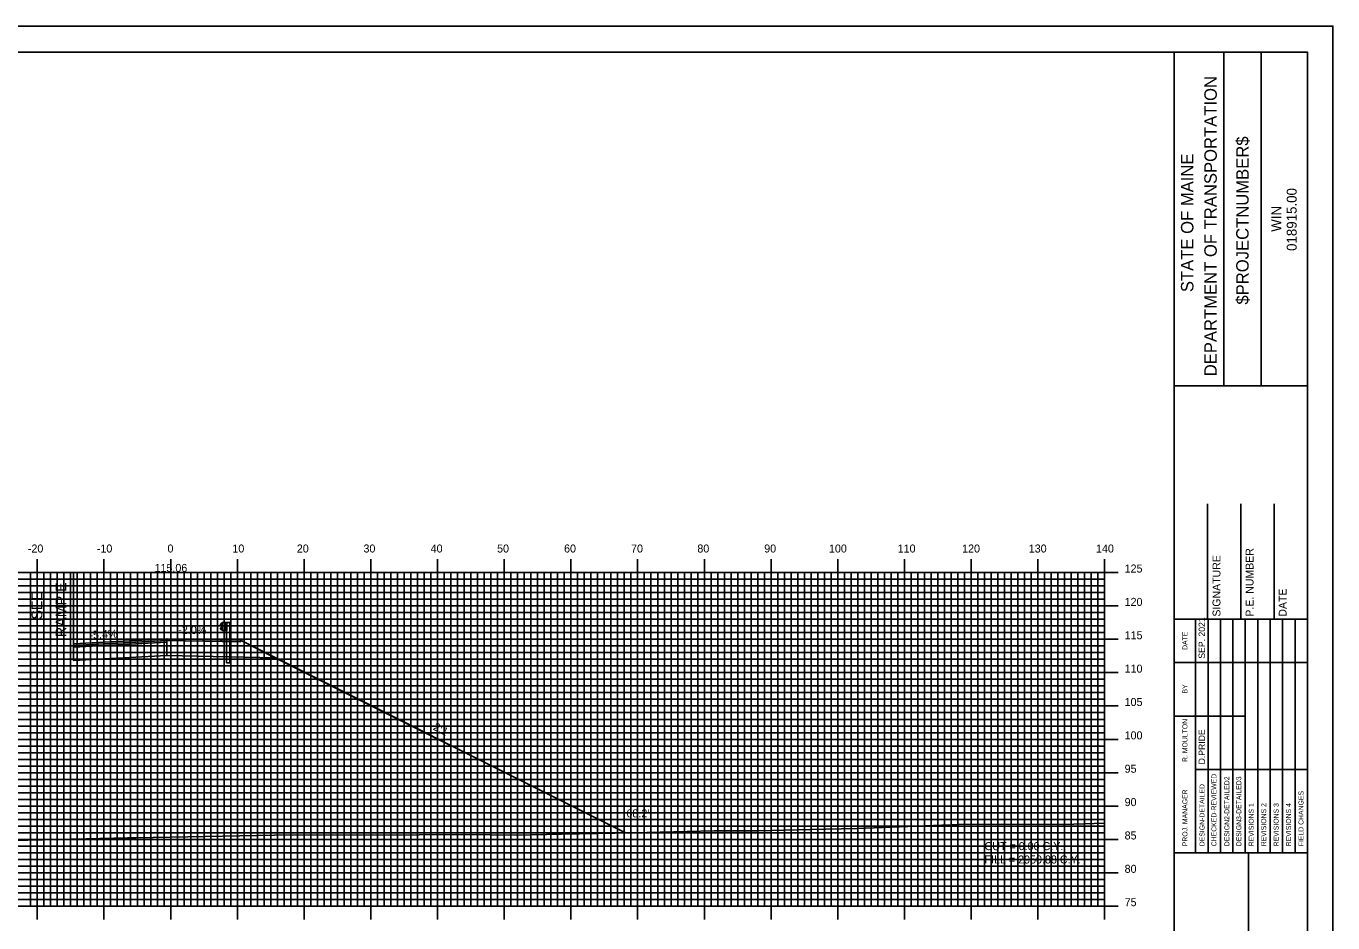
# Model space of a CAD drawing. Extents: x 92 to 435, y -1658 to -1438.
# Drawn here: x 236 to 431.8, y -1572.1 to -1437.7 of the extents above; entities that cross this region are included whole.
import ezdxf

# ---------------------------------------------------------------- set-up
doc = ezdxf.new("R2010")
doc.units = 0
for name, color, linetype in [('ANNOTATION', 7, 'Continuous'), ('BORDER', 7, 'Continuous'), ('D_Guardrail_Beam_Rt', 7, 'Continuous'), ('D_Roadway_Centerline', 7, 'Continuous'), ('D_Roadway_Centerline_Text', 7, 'Continuous'), ('D_Roadway_Edge_Shoulder', 7, 'Continuous'), ('D_Roadway_Edge_TW', 7, 'Continuous'), ('D_Roadway_Pavement', 7, 'Continuous'), ('D_Roadway_SlopeLines', 7, 'Continuous'), ('D_Roadway_SubGrade', 7, 'Continuous'), ('D_Text_Standard', 7, 'Continuous'), ('H_V ANNOTATION', 7, 'Continuous'), ('MAJOR', 7, 'Continuous'), ('MINOR', 7, 'Continuous'), ('PLOT BOUNDARY', 7, 'Continuous'), ('S_Roadway_Centerline', 7, 'Continuous')]:
    doc.layers.add(name, color=color, linetype=linetype)

msp = doc.modelspace()

# ---------------------------------------------------------------- linework, layer by layer
at = {"layer": 'BORDER'}
for p, q in [((408.02, -1651.6), (408.02, -1441.6)), ((415.48, -1491.61), (415.48, -1441.61)), ((421.07, -1491.61), (421.07, -1441.61)), ((408.02, -1491.62), (428.02, -1491.62)), ((413.02, -1526.6), (413.02, -1509.3)), ((418.02, -1526.6), (418.02, -1509.3)), ((423.02, -1526.6), (423.02, -1509.3)), ((408.02, -1526.6), (428.02, -1526.6)), ((408.02, -1561.6), (428.02, -1561.6)), ((419.2, -1631.6), (419.2, -1561.6))]:
    msp.add_line(p, q, dxfattribs=at)
msp.add_lwpolyline([(108.02, -1651.6), (428.02, -1651.6), (428.02, -1441.6), (108.02, -1441.6)], close=True, dxfattribs=at)
for points in [[(411.25, -1533.1), (411.25, -1526.6)], [(413.12, -1561.59), (413.12, -1526.6)], [(414.98, -1526.6), (414.98, -1561.59)], [(416.84, -1561.59), (416.84, -1526.6)], [(418.71, -1561.59), (418.71, -1526.6)], [(420.57, -1561.59), (420.57, -1526.6)], [(422.43, -1561.59), (422.43, -1526.6)], [(424.3, -1561.59), (424.3, -1526.6)], [(426.16, -1561.59), (426.16, -1526.6)], [(411.25, -1561.59), (411.25, -1528.01)], [(408.02, -1533.1), (428.02, -1533.1)], [(408.02, -1541.1), (411.25, -1541.1)], [(411.25, -1541.1), (418.7, -1541.1)], [(411.25, -1549.1), (428.02, -1549.1)]]:
    msp.add_lwpolyline(points, dxfattribs=at)
at = {"layer": 'D_Guardrail_Beam_Rt'}
for p, q in [((265.24, -1527.21), (265.1, -1527.31)), ((265.1, -1527.46), (265.29, -1527.59)), ((265.29, -1527.79), (265.1, -1527.93)), ((265.33, -1527.19), (265.26, -1527.21)), ((265.33, -1527.11), (266.02, -1527.11)), ((265.33, -1528.28), (265.33, -1527.11)), ((265.33, -1527.66), (265.33, -1527.73)), ((265.85, -1527.11), (265.85, -1528.28)), ((265.96, -1527.11), (265.96, -1528.28)), ((266.02, -1527.11), (266.49, -1527.11)), ((266.02, -1527.11), (266.02, -1528.28)), ((266.49, -1527.11), (266.49, -1533.11)), ((265.1, -1528.07), (265.24, -1528.17)), ((265.26, -1528.18), (265.33, -1528.19)), ((266.02, -1528.28), (265.33, -1528.28)), ((266, -1533.11), (266, -1528.28)), ((266, -1533.11), (266.49, -1533.11))]:
    msp.add_line(p, q, dxfattribs=at)
for centre, major_axis, start_param, end_param in [((265.15, -1527.39), (-0.0877, 0), 5.323254, 7.243116), ((265.26, -1527.25), (-0.0417, 0), 4.907132, 5.323254), ((265.25, -1527.66), (0.0789, 0), 0, 0.959931), ((265.25, -1527.73), (0.0789, 0), 5.323254, 6.283185), ((265.15, -1528), (-0.0877, 0), 5.323254, 7.243116), ((265.26, -1528.14), (-0.0417, 0), 0.959931, 1.376053)]:
    msp.add_ellipse(centre, major_axis=major_axis, ratio=0.995501, start_param=start_param, end_param=end_param, dxfattribs=at)
at = {"layer": 'D_Roadway_Centerline'}
msp.add_lwpolyline([(243.06, -1530.29), (257.06, -1529.53), (265.06, -1529.69), (268.06, -1529.75), (273.27, -1532.36), (325.78, -1558.61)], dxfattribs=at)
at = {"layer": 'D_Roadway_Edge_Shoulder'}
msp.add_lwpolyline([(257.06, -1529.53), (265.06, -1529.69), (265.06, -1529.69), (268.06, -1529.75), (268.06, -1530), (257.06, -1529.78)], close=True, dxfattribs=at)
at = {"layer": 'D_Roadway_Edge_TW'}
msp.add_lwpolyline([(243.06, -1530.29), (257.06, -1529.53), (257.06, -1529.78), (243.06, -1530.54)], close=True, dxfattribs=at)
at = {"layer": 'D_Roadway_Pavement'}
msp.add_lwpolyline([(243.06, -1530.54), (257.06, -1529.78), (257.06, -1530.03), (243.06, -1530.79)], close=True, dxfattribs=at)
msp.add_lwpolyline([(257.06, -1529.78), (257.06, -1530.03)], dxfattribs=at)
msp.add_lwpolyline([(257.06, -1529.78), (257.06, -1530.03)], dxfattribs=at)
at = {"layer": 'D_Roadway_SlopeLines'}
msp.add_lwpolyline([(268.06, -1529.75), (325.78, -1558.61)], dxfattribs=at)
at = {"layer": 'D_Roadway_SubGrade'}
msp.add_line((243.06, -1519.65), (243.06, -1532.79), dxfattribs=at)
for points in [[(257.06, -1530.03), (257.06, -1529.78), (268.06, -1530), (268.06, -1529.75), (273.27, -1532.36), (257.06, -1532.03)], [(243.06, -1530.79), (257.06, -1530.03), (257.06, -1532.03), (243.06, -1532.79)]]:
    msp.add_lwpolyline(points, close=True, dxfattribs=at)
at = {"layer": 'MAJOR'}
for p, q in [((237.62, -1517.6), (237.62, -1519.6)), ((247.62, -1517.6), (247.62, -1519.6)), ((257.62, -1517.6), (257.62, -1519.6)), ((267.62, -1517.6), (267.62, -1519.6)), ((277.62, -1517.6), (277.62, -1519.6)), ((287.62, -1517.6), (287.62, -1519.6)), ((297.62, -1517.6), (297.62, -1519.6)), ((307.62, -1517.6), (307.62, -1519.6)), ((317.62, -1517.6), (317.62, -1519.6)), ((327.62, -1517.6), (327.62, -1519.6)), ((337.62, -1517.6), (337.62, -1519.6)), ((347.62, -1517.6), (347.62, -1519.6)), ((357.62, -1517.6), (357.62, -1519.6)), ((367.62, -1517.6), (367.62, -1519.6)), ((377.62, -1517.6), (377.62, -1519.6)), ((387.62, -1517.6), (387.62, -1519.6)), ((397.62, -1517.6), (397.62, -1519.6)), ((117.62, -1519.6), (397.62, -1519.6)), ((117.62, -1519.6), (397.62, -1519.6)), ((237.62, -1569.6), (237.62, -1519.6)), ((247.62, -1569.6), (247.62, -1519.6)), ((257.62, -1569.6), (257.62, -1519.6)), ((267.62, -1569.6), (267.62, -1519.6)), ((277.62, -1569.6), (277.62, -1519.6)), ((287.62, -1569.6), (287.62, -1519.6)), ((297.62, -1569.6), (297.62, -1519.6)), ((307.62, -1569.6), (307.62, -1519.6)), ((317.62, -1569.6), (317.62, -1519.6)), ((327.62, -1569.6), (327.62, -1519.6)), ((337.62, -1569.6), (337.62, -1519.6)), ((347.62, -1569.6), (347.62, -1519.6)), ((357.62, -1569.6), (357.62, -1519.6)), ((367.62, -1569.6), (367.62, -1519.6)), ((377.62, -1569.6), (377.62, -1519.6)), ((387.62, -1569.6), (387.62, -1519.6)), ((399.63, -1519.6), (395.62, -1519.6)), ((397.62, -1569.6), (397.62, -1519.6)), ((397.62, -1569.6), (397.62, -1519.6)), ((117.62, -1524.6), (397.62, -1524.6)), ((399.63, -1524.6), (395.62, -1524.6)), ((117.62, -1529.6), (397.62, -1529.6)), ((399.63, -1529.6), (395.62, -1529.6)), ((117.62, -1534.6), (397.62, -1534.6)), ((399.63, -1534.6), (395.62, -1534.6)), ((117.62, -1539.6), (397.62, -1539.6)), ((399.63, -1539.6), (395.62, -1539.6)), ((117.62, -1544.6), (397.62, -1544.6)), ((399.63, -1544.6), (395.62, -1544.6)), ((117.62, -1549.6), (397.62, -1549.6)), ((399.63, -1549.6), (395.62, -1549.6)), ((117.62, -1554.6), (397.62, -1554.6)), ((399.63, -1554.6), (395.62, -1554.6)), ((117.62, -1559.6), (397.62, -1559.6)), ((399.63, -1559.6), (395.62, -1559.6)), ((117.62, -1564.6), (397.62, -1564.6)), ((399.63, -1564.6), (395.62, -1564.6)), ((117.62, -1569.6), (397.62, -1569.6)), ((117.62, -1569.6), (397.62, -1569.6)), ((237.62, -1571.61), (237.62, -1569.6)), ((247.62, -1571.61), (247.62, -1569.6)), ((257.62, -1571.61), (257.62, -1569.6)), ((267.62, -1571.61), (267.62, -1569.6)), ((277.62, -1571.61), (277.62, -1569.6)), ((287.62, -1571.61), (287.62, -1569.6)), ((297.62, -1571.61), (297.62, -1569.6)), ((307.62, -1571.61), (307.62, -1569.6)), ((317.62, -1571.61), (317.62, -1569.6)), ((327.62, -1571.61), (327.62, -1569.6)), ((337.62, -1571.61), (337.62, -1569.6)), ((347.62, -1571.61), (347.62, -1569.6)), ((357.62, -1571.61), (357.62, -1569.6)), ((367.62, -1571.61), (367.62, -1569.6)), ((377.62, -1571.61), (377.62, -1569.6)), ((387.62, -1571.61), (387.62, -1569.6)), ((399.63, -1569.6), (395.62, -1569.6)), ((397.62, -1571.61), (397.62, -1569.6))]:
    msp.add_line(p, q, dxfattribs=at)
at = {"layer": 'MINOR'}
for p, q in [((236.62, -1569.6), (236.62, -1519.6)), ((238.62, -1569.6), (238.62, -1519.6)), ((239.62, -1569.6), (239.62, -1519.6)), ((240.62, -1569.6), (240.62, -1519.6)), ((241.62, -1569.6), (241.62, -1519.6)), ((242.62, -1569.6), (242.62, -1519.6)), ((243.62, -1569.6), (243.62, -1519.6)), ((244.62, -1569.6), (244.62, -1519.6)), ((245.62, -1569.6), (245.62, -1519.6)), ((246.62, -1569.6), (246.62, -1519.6)), ((248.62, -1569.6), (248.62, -1519.6)), ((249.62, -1569.6), (249.62, -1519.6)), ((250.62, -1569.6), (250.62, -1519.6)), ((251.62, -1569.6), (251.62, -1519.6)), ((252.62, -1569.6), (252.62, -1519.6)), ((253.62, -1569.6), (253.62, -1519.6)), ((254.62, -1569.6), (254.62, -1519.6)), ((255.62, -1569.6), (255.62, -1519.6)), ((256.62, -1569.6), (256.62, -1519.6)), ((258.62, -1569.6), (258.62, -1519.6)), ((259.62, -1569.6), (259.62, -1519.6)), ((260.62, -1569.6), (260.62, -1519.6)), ((261.62, -1569.6), (261.62, -1519.6)), ((262.62, -1569.6), (262.62, -1519.6)), ((263.62, -1569.6), (263.62, -1519.6)), ((264.62, -1569.6), (264.62, -1519.6)), ((265.62, -1569.6), (265.62, -1519.6)), ((266.62, -1569.6), (266.62, -1519.6)), ((268.62, -1569.6), (268.62, -1519.6)), ((269.62, -1569.6), (269.62, -1519.6)), ((270.62, -1569.6), (270.62, -1519.6)), ((271.62, -1569.6), (271.62, -1519.6)), ((272.62, -1569.6), (272.62, -1519.6)), ((273.62, -1569.6), (273.62, -1519.6)), ((274.62, -1569.6), (274.62, -1519.6)), ((275.62, -1569.6), (275.62, -1519.6)), ((276.62, -1569.6), (276.62, -1519.6)), ((278.62, -1569.6), (278.62, -1519.6)), ((279.62, -1569.6), (279.62, -1519.6)), ((280.62, -1569.6), (280.62, -1519.6)), ((281.62, -1569.6), (281.62, -1519.6)), ((282.62, -1569.6), (282.62, -1519.6)), ((283.62, -1569.6), (283.62, -1519.6)), ((284.62, -1569.6), (284.62, -1519.6)), ((285.62, -1569.6), (285.62, -1519.6)), ((286.62, -1569.6), (286.62, -1519.6)), ((288.62, -1569.6), (288.62, -1519.6)), ((289.62, -1569.6), (289.62, -1519.6)), ((290.62, -1569.6), (290.62, -1519.6)), ((291.62, -1569.6), (291.62, -1519.6)), ((292.62, -1569.6), (292.62, -1519.6)), ((293.62, -1569.6), (293.62, -1519.6)), ((294.62, -1569.6), (294.62, -1519.6)), ((295.62, -1569.6), (295.62, -1519.6)), ((296.62, -1569.6), (296.62, -1519.6)), ((298.62, -1569.6), (298.62, -1519.6)), ((299.62, -1569.6), (299.62, -1519.6)), ((300.62, -1569.6), (300.62, -1519.6)), ((301.62, -1569.6), (301.62, -1519.6)), ((302.62, -1569.6), (302.62, -1519.6)), ((303.62, -1569.6), (303.62, -1519.6)), ((304.62, -1569.6), (304.62, -1519.6)), ((305.62, -1569.6), (305.62, -1519.6)), ((306.62, -1569.6), (306.62, -1519.6)), ((308.62, -1569.6), (308.62, -1519.6)), ((309.62, -1569.6), (309.62, -1519.6)), ((310.62, -1569.6), (310.62, -1519.6)), ((311.62, -1569.6), (311.62, -1519.6)), ((312.62, -1569.6), (312.62, -1519.6)), ((313.62, -1569.6), (313.62, -1519.6)), ((314.62, -1569.6), (314.62, -1519.6)), ((315.62, -1569.6), (315.62, -1519.6)), ((316.62, -1569.6), (316.62, -1519.6)), ((318.62, -1569.6), (318.62, -1519.6)), ((319.62, -1569.6), (319.62, -1519.6)), ((320.62, -1569.6), (320.62, -1519.6)), ((321.62, -1569.6), (321.62, -1519.6)), ((322.62, -1569.6), (322.62, -1519.6)), ((323.62, -1569.6), (323.62, -1519.6)), ((324.62, -1569.6), (324.62, -1519.6)), ((325.62, -1569.6), (325.62, -1519.6)), ((326.62, -1569.6), (326.62, -1519.6)), ((328.62, -1569.6), (328.62, -1519.6)), ((329.62, -1569.6), (329.62, -1519.6)), ((330.62, -1569.6), (330.62, -1519.6)), ((331.62, -1569.6), (331.62, -1519.6)), ((332.62, -1569.6), (332.62, -1519.6)), ((333.62, -1569.6), (333.62, -1519.6)), ((334.62, -1569.6), (334.62, -1519.6)), ((335.62, -1569.6), (335.62, -1519.6)), ((336.62, -1569.6), (336.62, -1519.6)), ((338.62, -1569.6), (338.62, -1519.6)), ((339.62, -1569.6), (339.62, -1519.6)), ((340.62, -1569.6), (340.62, -1519.6)), ((341.62, -1569.6), (341.62, -1519.6)), ((342.62, -1569.6), (342.62, -1519.6)), ((343.62, -1569.6), (343.62, -1519.6)), ((344.62, -1569.6), (344.62, -1519.6)), ((345.62, -1569.6), (345.62, -1519.6)), ((346.62, -1569.6), (346.62, -1519.6)), ((348.62, -1569.6), (348.62, -1519.6)), ((349.62, -1569.6), (349.62, -1519.6)), ((350.62, -1569.6), (350.62, -1519.6)), ((351.62, -1569.6), (351.62, -1519.6)), ((352.62, -1569.6), (352.62, -1519.6)), ((353.62, -1569.6), (353.62, -1519.6)), ((354.62, -1569.6), (354.62, -1519.6)), ((355.62, -1569.6), (355.62, -1519.6)), ((356.62, -1569.6), (356.62, -1519.6)), ((358.62, -1569.6), (358.62, -1519.6)), ((359.62, -1569.6), (359.62, -1519.6)), ((360.62, -1569.6), (360.62, -1519.6)), ((361.62, -1569.6), (361.62, -1519.6)), ((362.62, -1569.6), (362.62, -1519.6)), ((363.62, -1569.6), (363.62, -1519.6)), ((364.62, -1569.6), (364.62, -1519.6)), ((365.62, -1569.6), (365.62, -1519.6)), ((366.62, -1569.6), (366.62, -1519.6)), ((368.62, -1569.6), (368.62, -1519.6)), ((369.62, -1569.6), (369.62, -1519.6)), ((370.62, -1569.6), (370.62, -1519.6)), ((371.62, -1569.6), (371.62, -1519.6)), ((372.62, -1569.6), (372.62, -1519.6)), ((373.62, -1569.6), (373.62, -1519.6)), ((374.62, -1569.6), (374.62, -1519.6)), ((375.62, -1569.6), (375.62, -1519.6)), ((376.62, -1569.6), (376.62, -1519.6)), ((378.62, -1569.6), (378.62, -1519.6)), ((379.62, -1569.6), (379.62, -1519.6)), ((380.62, -1569.6), (380.62, -1519.6)), ((381.62, -1569.6), (381.62, -1519.6)), ((382.62, -1569.6), (382.62, -1519.6)), ((383.62, -1569.6), (383.62, -1519.6)), ((384.62, -1569.6), (384.62, -1519.6)), ((385.62, -1569.6), (385.62, -1519.6)), ((386.62, -1569.6), (386.62, -1519.6)), ((388.62, -1569.6), (388.62, -1519.6)), ((389.62, -1569.6), (389.62, -1519.6)), ((390.62, -1569.6), (390.62, -1519.6)), ((391.62, -1569.6), (391.62, -1519.6)), ((392.62, -1569.6), (392.62, -1519.6)), ((393.62, -1569.6), (393.62, -1519.6)), ((394.62, -1569.6), (394.62, -1519.6)), ((395.62, -1569.6), (395.62, -1519.6)), ((396.62, -1569.6), (396.62, -1519.6)), ((117.62, -1520.6), (397.62, -1520.6)), ((117.62, -1521.6), (397.62, -1521.6)), ((397.62, -1520.6), (395.62, -1520.6)), ((397.62, -1521.6), (395.62, -1521.6)), ((117.62, -1522.6), (397.62, -1522.6)), ((117.62, -1523.6), (397.62, -1523.6)), ((397.62, -1522.6), (395.62, -1522.6)), ((397.62, -1523.6), (395.62, -1523.6)), ((117.62, -1525.6), (397.62, -1525.6)), ((397.62, -1525.6), (395.62, -1525.6)), ((117.62, -1526.6), (397.62, -1526.6)), ((117.62, -1527.6), (397.62, -1527.6)), ((397.62, -1526.6), (395.62, -1526.6)), ((397.62, -1527.6), (395.62, -1527.6)), ((117.62, -1528.6), (397.62, -1528.6)), ((397.62, -1528.6), (395.62, -1528.6)), ((117.62, -1530.6), (397.62, -1530.6)), ((117.62, -1531.6), (397.62, -1531.6)), ((397.62, -1530.6), (395.62, -1530.6)), ((397.62, -1531.6), (395.62, -1531.6)), ((117.62, -1532.6), (397.62, -1532.6)), ((117.62, -1533.6), (397.62, -1533.6)), ((397.62, -1532.6), (395.62, -1532.6)), ((397.62, -1533.6), (395.62, -1533.6)), ((117.62, -1535.6), (397.62, -1535.6)), ((397.62, -1535.6), (395.62, -1535.6)), ((117.62, -1536.6), (397.62, -1536.6)), ((117.62, -1537.6), (397.62, -1537.6)), ((397.62, -1536.6), (395.62, -1536.6)), ((397.62, -1537.6), (395.62, -1537.6)), ((117.62, -1538.6), (397.62, -1538.6)), ((397.62, -1538.6), (395.62, -1538.6)), ((117.62, -1540.6), (397.62, -1540.6)), ((117.62, -1541.6), (397.62, -1541.6)), ((397.62, -1540.6), (395.62, -1540.6)), ((397.62, -1541.6), (395.62, -1541.6)), ((117.62, -1542.6), (397.62, -1542.6)), ((397.62, -1542.6), (395.62, -1542.6)), ((117.62, -1543.6), (397.62, -1543.6)), ((397.62, -1543.6), (395.62, -1543.6)), ((117.62, -1545.6), (397.62, -1545.6)), ((117.62, -1546.6), (397.62, -1546.6)), ((397.62, -1545.6), (395.62, -1545.6)), ((397.62, -1546.6), (395.62, -1546.6)), ((117.62, -1547.6), (397.62, -1547.6)), ((117.62, -1548.6), (397.62, -1548.6)), ((397.62, -1547.6), (395.62, -1547.6)), ((397.62, -1548.6), (395.62, -1548.6)), ((117.62, -1550.6), (397.62, -1550.6)), ((397.62, -1550.6), (395.62, -1550.6)), ((117.62, -1551.6), (397.62, -1551.6)), ((117.62, -1552.6), (397.62, -1552.6)), ((397.62, -1551.6), (395.62, -1551.6)), ((397.62, -1552.6), (395.62, -1552.6)), ((117.62, -1553.6), (397.62, -1553.6)), ((397.62, -1553.6), (395.62, -1553.6)), ((117.62, -1555.6), (397.62, -1555.6)), ((117.62, -1556.6), (397.62, -1556.6)), ((397.62, -1555.6), (395.62, -1555.6)), ((397.62, -1556.6), (395.62, -1556.6)), ((117.62, -1557.6), (397.62, -1557.6)), ((117.62, -1558.6), (397.62, -1558.6)), ((397.62, -1557.6), (395.62, -1557.6)), ((397.62, -1558.6), (395.62, -1558.6)), ((117.62, -1560.6), (397.62, -1560.6)), ((397.62, -1560.6), (395.62, -1560.6)), ((117.62, -1561.6), (397.62, -1561.6)), ((117.62, -1562.6), (397.62, -1562.6)), ((397.62, -1561.6), (395.62, -1561.6)), ((397.62, -1562.6), (395.62, -1562.6)), ((117.62, -1563.6), (397.62, -1563.6)), ((397.62, -1563.6), (395.62, -1563.6)), ((117.62, -1565.6), (397.62, -1565.6)), ((117.62, -1566.6), (397.62, -1566.6)), ((397.62, -1565.6), (395.62, -1565.6)), ((397.62, -1566.6), (395.62, -1566.6)), ((117.62, -1567.6), (397.62, -1567.6)), ((117.62, -1568.6), (397.62, -1568.6)), ((397.62, -1567.6), (395.62, -1567.6)), ((397.62, -1568.6), (395.62, -1568.6))]:
    msp.add_line(p, q, dxfattribs=at)
at = {"layer": 'PLOT BOUNDARY'}
msp.add_lwpolyline([(91.83, -1657.72), (431.83, -1657.72), (431.83, -1437.72), (91.83, -1437.72)], close=True, dxfattribs=at)
at = {"layer": 'S_Roadway_Centerline'}
msp.add_lwpolyline([(229.62, -1559.88), (244.97, -1559.52), (251.16, -1559.38), (252.4, -1559.34), (273.19, -1558.95), (274.52, -1558.93), (275.93, -1558.94), (294.89, -1558.92), (301.57, -1558.85), (309.43, -1558.94), (316.22, -1558.83), (326.95, -1558.59), (339.08, -1558.32), (345.68, -1558.32), (353.49, -1558.13), (360.55, -1557.95), (375.75, -1557.37), (382.2, -1557.29), (391.48, -1557.36), (397.62, -1557.16)], dxfattribs=at)

# ---------------------------------------------------------------- texts
at = {"layer": 'ANNOTATION'}
for s, height, rotation, p in [('RAMP E', 1.6, 90, (241.97, -1529.28)), ('SEE', 1.6, 90, (238.37, -1526.66)), ('-2.0%', 1.2, 358.8535, (258.75, -1528.77)), ('-5.4%', 1.2, 3.0788, (245.47, -1529.56)), ('2:1', 1.2, 333.4349, (296.85, -1543.11))]:
    msp.add_text(s, height=height, rotation=rotation, dxfattribs=at).set_placement(p)
at = {"layer": 'BORDER'}
for s, height, p in [('DEPARTMENT OF TRANSPORTATION', 1.8635, (414.43, -1490.19)), ('$PROJECTNUMBER$', 1.8635, (419.21, -1479.45)), ('STATE OF MAINE', 1.8635, (410.93, -1477.58)), ('018915.00', 1.491, (426.41, -1471.41)), ('WIN', 1.491, (424.09, -1468.54)), ('P.E. NUMBER', 1.1811, (419.94, -1526.21)), ('SIGNATURE', 1.181, (414.98, -1526.21)), ('DATE', 1.181, (424.9, -1526.21)), ('SEP. 2021', 0.969, (412.67, -1532.51)), ('DATE', 0.743, (410.03, -1531.19)), ('BY', 0.743, (410.03, -1537.73)), ('R. MOULTON', 0.745, (410.03, -1547.99)), ('D.PRIDE', 0.969, (412.67, -1548.35)), ('CHECKED-REVIEWED', 0.7455, (414.38, -1560.62)), ('DESIGN2-DETAILED2', 0.7455, (416.32, -1560.62)), ('DESIGN3-DETAILED3', 0.7455, (418.11, -1560.62)), ('PROJ. MANAGER', 0.7455, (410.03, -1560.62)), ('DESIGN-DETAILED', 0.7455, (412.59, -1560.62)), ('FIELD CHANGES', 0.7455, (427.43, -1560.62)), ('REVISIONS 1', 0.7455, (419.97, -1560.62)), ('REVISIONS 2', 0.7455, (421.84, -1560.62)), ('REVISIONS 3', 0.7455, (423.7, -1560.62)), ('REVISIONS 4', 0.7455, (425.56, -1560.62))]:
    msp.add_text(s, height=height, rotation=90, dxfattribs=at).set_placement(p)
at = {"layer": 'D_Roadway_Centerline_Text'}
msp.add_text('115.06', height=1.2, dxfattribs=at).set_placement((255.2, -1519.51))
at = {"layer": 'D_Text_Standard'}
for s, p in [("68.2'", (325.94, -1556.29)), ('CUT = 0.00 C.Y.', (379.62, -1561.2)), ('FILL = 2950.88 C.Y.', (379.62, -1563.2))]:
    msp.add_text(s, height=1.2, dxfattribs=at).set_placement(p)
at = {"layer": 'H_V ANNOTATION'}
for s, p in [('-20', (236.21, -1516.6)), ('-10', (246.55, -1516.6)), ('0', (257.14, -1516.6)), ('10', (266.87, -1516.6)), ('20', (276.53, -1516.6)), ('30', (286.52, -1516.6)), ('40', (296.59, -1516.6)), ('50', (306.55, -1516.6)), ('60', (316.59, -1516.6)), ('70', (326.63, -1516.6)), ('80', (336.57, -1516.6)), ('90', (346.59, -1516.6)), ('100', (356.3, -1516.6)), ('110', (366.6, -1516.6)), ('120', (376.26, -1516.6)), ('130', (386.25, -1516.6)), ('140', (396.33, -1516.6)), ('125', (400.62, -1519.6)), ('120', (400.62, -1524.6)), ('115', (400.62, -1529.6)), ('110', (400.62, -1534.6)), ('105', (400.62, -1539.6)), ('100', (400.62, -1544.6)), ('95', (400.62, -1549.6)), ('90', (400.62, -1554.6)), ('85', (400.62, -1559.6)), ('80', (400.62, -1564.6)), ('75', (400.62, -1569.6))]:
    msp.add_text(s, height=1.2, dxfattribs=at).set_placement(p)

doc.saveas('drawing.dxf')
